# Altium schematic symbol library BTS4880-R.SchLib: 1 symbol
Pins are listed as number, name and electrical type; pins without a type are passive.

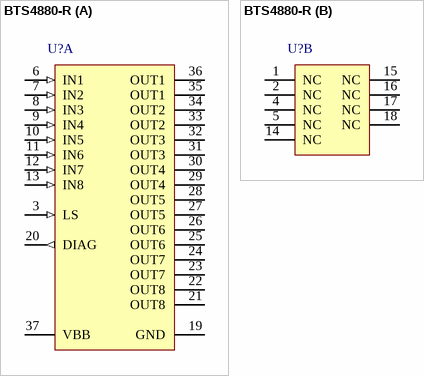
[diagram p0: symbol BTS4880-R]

## BTS4880-R
designator U?
Smart Power High-Side-Switch, 8 Channels: 8 x 200 mOhm, -40 to 150 degC, PG-DSO-36-26, Reel, Green; Manufacturer: Infineon; PartNumber: BTS4880-R; Channels: 8; Green: TRUE; Group: Automotive Qualified; Ptot (max): 3.3 W; Recommended Operating Voltage Max.: 45 V; Recommended Operating Voltage Min.: 11 V; RON(max) @ 150degreesC: 320 mOhm; toff (max): 150 us; ton (max): 100 us
footprint INF-PG-DSO-36-26_N (SOP, 36-Leads, Body 15.9x11mm, Pitch 0.65mm, Thermal Pad 16x6mm, IPC Medium Density)
footprint INF-PG-DSO-36-26_L (SOP, 36-Leads, Body 15.9x11mm, Pitch 0.65mm, Thermal Pad 16x6mm, IPC High Density)
footprint INF-PG-DSO-36-26_M (SOP, 36-Leads, Body 15.9x11mm, Pitch 0.65mm, Thermal Pad 16x6mm, IPC Low Density)
part A pins: 3 LS (in) "Enable pin for switching the input-levels to Vbb/2", 6 IN1 (in) "Input, activeates channel 1 in case of logic high signal", 7 IN2 (in) "Input, activeates channel 2 in case of logic high signal", 8 IN3 (in) "Input, activeates channel 3 in case of logic high signal", 9 IN4 (in) "Input, activeates channel 4 in case of logic high signal", 10 IN5 (in) "Input, activeates channel 5 in case of logic high signal", 11 IN6 (in) "Input, activeates channel 6 in case of logic high signal", 12 IN7 (in) "Input, activeates channel 7 in case of logic high signal", 13 IN8 (in) "Input, activeates channel 8 in case of logic high signal", 19 GND (power) "Logic ground", 20 DIAG (out) "Common diagnostic output for overtemperature", 21 OUT8 (power) "High-side output of channel 8", 22 OUT8 (power) "High-side output of channel 8", 23 OUT7 (power) "High-side output of channel 7", 24 OUT7 (power) "High-side output of channel 7", 25 OUT6 (power) "High-side output of channel 6", 26 OUT6 (power) "High-side output of channel 6", 27 OUT5 (power) "High-side output of channel 5", 28 OUT5 (power) "High-side output of channel 5", 29 OUT4 (power) "High-side output of channel 4", 30 OUT4 (power) "High-side output of channel 4", 31 OUT3 (power) "High-side output of channel 3", 32 OUT3 (power) "High-side output of channel 3", 33 OUT2 (power) "High-side output of channel 2", 34 OUT2 (power) "High-side output of channel 2", 35 OUT1 (power) "High-side output of channel 1", 36 OUT1 (power) "High-side output of channel 1", 37 VBB (power) "Positive power supply voltage"
part B pins: 1 NC "not connected", 2 NC "not connected", 4 NC "not connected", 5 NC "not connected", 14 NC "not connected", 15 NC "not connected", 16 NC "not connected", 17 NC "not connected", 18 NC "not connected"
